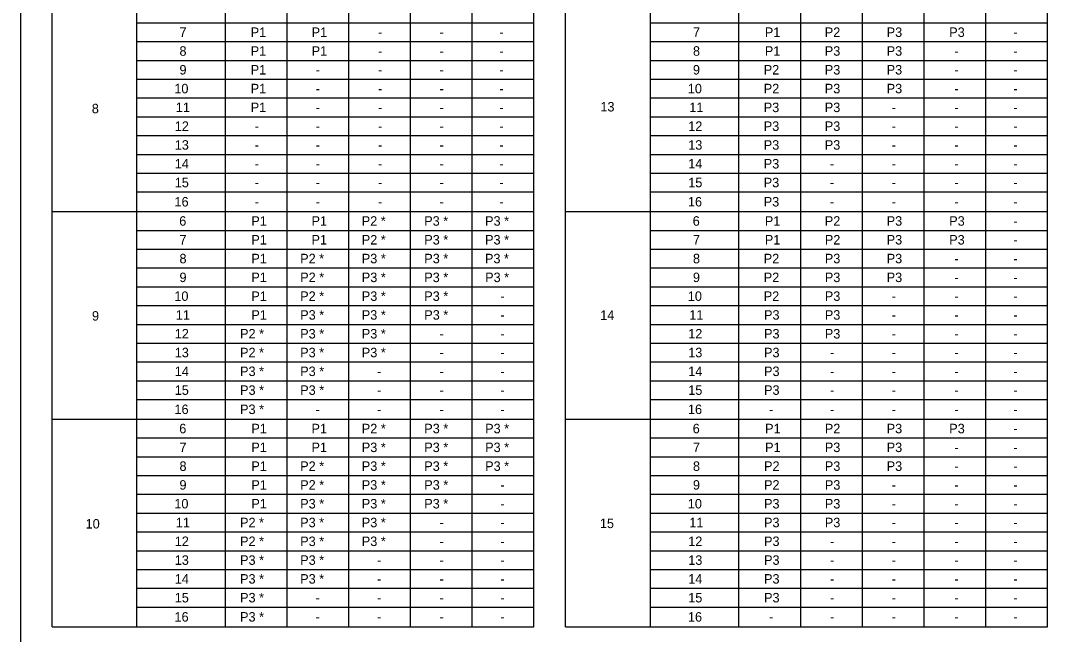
# Model space of a CAD drawing. Extents: x -2340 to 628, y -879 to 309.
# Drawn here: x -1077.4 to -752.7, y -78.6 to 115.5 of the extents above; entities that cross this region are included whole.
import ezdxf

# ---------------------------------------------------------------- set-up
doc = ezdxf.new("R2010")
doc.units = 0
for name, color, linetype in [('Level 1', 7, 'Continuous'), ('Level 2', 7, 'Continuous'), ('Level 30', 7, 'Continuous')]:
    doc.layers.add(name, color=color, linetype=linetype)

msp = doc.modelspace()

# ---------------------------------------------------------------- linework, layer by layer
at = {"layer": 'Level 1'}
for p, q in [((-1077.39, 294.44), (-1077.39, -269.56)), ((-878.24, -76.15), (-878.24, 270.25)), ((-850.23, -76.15), (-850.23, 270.25)), ((-830.72, -76.15), (-830.72, 262.9)), ((-811.22, -76.15), (-811.22, 262.9)), ((-791.71, -76.15), (-791.71, 262.9)), ((-772.2, -76.15), (-772.2, 262.9)), ((-1067.39, -76.15), (-1067.39, 251.9)), ((-915.04, -76.15), (-915.04, 251.9)), ((-905.04, -76.15), (-905.04, 251.9)), ((-752.69, -76.15), (-752.69, 251.9)), ((-878.24, 114.74), (-752.69, 114.74)), ((-878.24, 108.8), (-752.69, 108.8)), ((-878.24, 102.86), (-752.69, 102.86)), ((-878.24, 96.92), (-752.69, 96.92)), ((-878.24, 90.98), (-752.69, 90.98)), ((-878.24, 85.04), (-752.69, 85.04)), ((-878.24, 79.1), (-752.69, 79.1)), ((-878.24, 73.16), (-752.69, 73.16)), ((-878.24, 67.22), (-752.69, 67.22)), ((-878.24, 61.28), (-752.69, 61.28)), ((-974.24, 55.07), (-938.6, 55.07)), ((-938.6, 55.07), (-915.04, 55.07)), ((-905.04, 55.07), (-752.69, 55.07)), ((-878.24, 49.13), (-752.69, 49.13)), ((-878.24, 43.19), (-752.69, 43.19)), ((-878.24, 37.25), (-752.69, 37.25)), ((-878.24, 31.31), (-752.69, 31.31)), ((-878.24, 25.37), (-752.69, 25.37)), ((-878.24, 19.43), (-752.69, 19.43)), ((-878.24, 13.49), (-752.69, 13.49)), ((-878.24, 7.55), (-752.69, 7.55)), ((-878.24, 1.61), (-752.69, 1.61)), ((-878.24, -4.33), (-752.69, -4.33)), ((-905.04, -10.54), (-752.69, -10.54)), ((-878.24, -16.48), (-752.69, -16.48)), ((-878.24, -22.42), (-752.69, -22.42)), ((-878.24, -28.36), (-752.69, -28.36)), ((-878.24, -34.3), (-752.69, -34.3)), ((-878.24, -40.24), (-752.69, -40.24)), ((-878.24, -46.18), (-752.69, -46.18)), ((-878.24, -52.12), (-752.69, -52.12)), ((-878.24, -58.06), (-752.69, -58.06)), ((-878.24, -64), (-752.69, -64)), ((-878.24, -69.94), (-752.69, -69.94)), ((-905.04, -76.15), (-752.69, -76.15))]:
    msp.add_line(p, q, dxfattribs=at)
at = {"layer": 'Level 2'}
for p, q in [((-1040.58, -76.15), (-1040.58, 251.9)), ((-1012.58, -76.15), (-1012.58, 251.9)), ((-993.07, -76.15), (-993.07, 251.9)), ((-973.56, -76.15), (-973.56, 251.9)), ((-954.05, -76.15), (-954.05, 251.9)), ((-934.55, -76.15), (-934.55, 251.9)), ((-1040.58, 114.74), (-915.04, 114.74)), ((-974.24, 114.74), (-938.6, 114.74)), ((-1040.58, 108.8), (-915.04, 108.8)), ((-974.24, 108.8), (-938.6, 108.8)), ((-1040.58, 102.86), (-915.04, 102.86)), ((-974.24, 102.86), (-938.6, 102.86)), ((-1040.58, 96.92), (-915.04, 96.92)), ((-974.24, 96.92), (-938.6, 96.92)), ((-1040.58, 90.98), (-915.04, 90.98)), ((-974.24, 90.98), (-938.6, 90.98)), ((-1040.58, 85.04), (-915.04, 85.04)), ((-1040.58, 79.1), (-915.04, 79.1)), ((-1040.58, 73.16), (-915.04, 73.16)), ((-1040.58, 67.22), (-915.04, 67.22)), ((-1040.58, 61.28), (-915.04, 61.28)), ((-1067.39, 55.07), (-915.04, 55.07)), ((-1040.58, 49.13), (-915.04, 49.13)), ((-1040.58, 43.19), (-915.04, 43.19)), ((-1040.58, 37.25), (-915.04, 37.25)), ((-1040.58, 31.31), (-915.04, 31.31)), ((-1040.58, 25.37), (-915.04, 25.37)), ((-1040.58, 19.43), (-915.04, 19.43)), ((-1040.58, 13.49), (-915.04, 13.49)), ((-1040.58, 7.55), (-915.04, 7.55)), ((-1040.58, 1.61), (-915.04, 1.61)), ((-1040.58, -4.33), (-915.04, -4.33)), ((-1067.39, -10.54), (-915.04, -10.54)), ((-1040.58, -16.48), (-915.04, -16.48)), ((-1040.58, -22.42), (-915.04, -22.42)), ((-1040.58, -28.36), (-915.04, -28.36)), ((-1040.58, -34.3), (-915.04, -34.3)), ((-1040.58, -40.24), (-915.04, -40.24)), ((-1040.58, -46.18), (-915.04, -46.18)), ((-1040.58, -52.12), (-915.04, -52.12)), ((-1040.58, -58.06), (-915.04, -58.06)), ((-1040.58, -64), (-915.04, -64)), ((-1040.58, -69.94), (-915.04, -69.94)), ((-974.24, -69.94), (-938.6, -69.94)), ((-1067.39, -76.15), (-915.04, -76.15))]:
    msp.add_line(p, q, dxfattribs=at)

# ---------------------------------------------------------------- texts
at = {"layer": 'Level 1'}
for s, p in [('P1', (-842.06, 110.27)), ('P2', (-823.1, 110.27)), ('P3', (-803.53, 110.27)), ('P3', (-783.76, 110.27)), ('-', (-763.44, 110.27)), ('P1', (-842.06, 104.33)), ('P3', (-823.1, 104.33)), ('P3', (-803.53, 104.33)), ('-', (-782.14, 104.33)), ('-', (-763.44, 104.33)), ('P2', (-842.4, 98.39)), ('P3', (-823.1, 98.39)), ('P3', (-803.53, 98.39)), ('-', (-782.14, 98.39)), ('-', (-763.44, 98.39)), ('P2', (-842.4, 92.45)), ('P3', (-823.1, 92.45)), ('P3', (-803.53, 92.45)), ('-', (-782.14, 92.45)), ('-', (-763.44, 92.45)), ('13', (-894.06, 86.71)), ('P3', (-842.4, 86.51)), ('P3', (-823.1, 86.51)), ('-', (-801.91, 86.51)), ('-', (-782.14, 86.51)), ('-', (-763.44, 86.51)), ('P3', (-842.4, 80.57)), ('P3', (-823.1, 80.57)), ('-', (-801.91, 80.57)), ('-', (-782.14, 80.57)), ('-', (-763.44, 80.57)), ('P3', (-842.4, 74.63)), ('P3', (-823.1, 74.63)), ('-', (-801.92, 74.63)), ('-', (-782.14, 74.63)), ('-', (-763.44, 74.63)), ('P3', (-842.4, 68.69)), ('-', (-821.48, 68.69)), ('-', (-801.92, 68.69)), ('-', (-782.14, 68.69)), ('-', (-763.44, 68.69)), ('P3', (-842.4, 62.75)), ('-', (-821.48, 62.75)), ('-', (-801.92, 62.75)), ('-', (-782.14, 62.75)), ('-', (-763.44, 62.75)), ('P3', (-842.4, 56.68)), ('-', (-821.48, 56.68)), ('-', (-801.92, 56.68)), ('-', (-782.14, 56.68)), ('-', (-763.44, 56.68)), ('P1', (-842.06, 50.6)), ('P2', (-823.1, 50.6)), ('P3', (-803.53, 50.6)), ('P3', (-783.76, 50.6)), ('-', (-763.44, 50.6)), ('P1', (-842.06, 44.66)), ('P2', (-823.09, 44.66)), ('P3', (-803.53, 44.66)), ('P3', (-783.76, 44.66)), ('-', (-763.44, 44.66)), ('P2', (-842.4, 38.72)), ('P3', (-823.09, 38.72)), ('P3', (-803.53, 38.72)), ('-', (-782.14, 38.72)), ('-', (-763.44, 38.72)), ('P2', (-842.4, 32.78)), ('P3', (-823.09, 32.78)), ('P3', (-803.53, 32.78)), ('-', (-782.14, 32.78)), ('-', (-763.44, 32.78)), ('P2', (-842.4, 26.84)), ('P3', (-823.09, 26.84)), ('-', (-801.92, 26.84)), ('-', (-782.14, 26.84)), ('-', (-763.44, 26.84)), ('14', (-894.11, 20.82)), ('P3', (-842.31, 20.9)), ('P3', (-823.09, 20.9)), ('-', (-801.92, 20.9)), ('-', (-782.14, 20.9)), ('-', (-763.44, 20.9)), ('P3', (-842.31, 14.96)), ('P3', (-823.09, 14.96)), ('-', (-801.92, 14.96)), ('-', (-782.14, 14.96)), ('-', (-763.44, 14.96)), ('P3', (-842.31, 9.02)), ('-', (-821.47, 9.02)), ('-', (-801.92, 9.02)), ('-', (-782.13, 9.02)), ('-', (-763.44, 9.02)), ('P3', (-842.31, 3.08)), ('-', (-821.47, 3.08)), ('-', (-801.92, 3.08)), ('-', (-782.13, 3.08)), ('-', (-763.44, 3.08)), ('P3', (-842.31, -2.86)), ('-', (-821.47, -2.86)), ('-', (-801.92, -2.86)), ('-', (-782.13, -2.86)), ('-', (-763.44, -2.86)), ('-', (-840.7, -8.93)), ('-', (-821.47, -8.93)), ('-', (-801.92, -8.93)), ('-', (-782.13, -8.93)), ('-', (-763.44, -8.93)), ('P1', (-841.97, -15.01)), ('P2', (-823.09, -15.01)), ('P3', (-803.53, -15.01)), ('P3', (-783.75, -15.01)), ('-', (-763.44, -15.01)), ('P1', (-841.97, -20.95)), ('P3', (-823.09, -20.95)), ('P3', (-803.53, -20.95)), ('-', (-782.13, -20.95)), ('-', (-763.44, -20.95)), ('P2', (-842.31, -26.89)), ('P3', (-823.09, -26.89)), ('P3', (-803.53, -26.89)), ('-', (-782.13, -26.89)), ('-', (-763.44, -26.89)), ('P2', (-842.31, -32.83)), ('P3', (-823.09, -32.83)), ('-', (-801.92, -32.83)), ('-', (-782.13, -32.83)), ('-', (-763.44, -32.83)), ('P3', (-842.31, -38.77)), ('P3', (-823.09, -38.77)), ('-', (-801.92, -38.77)), ('-', (-782.13, -38.77)), ('-', (-763.44, -38.77)), ('15', (-894.21, -44.98)), ('P3', (-842.31, -44.71)), ('P3', (-823.09, -44.71)), ('-', (-801.92, -44.71)), ('-', (-782.13, -44.71)), ('-', (-763.44, -44.71)), ('P3', (-842.31, -50.65)), ('-', (-821.47, -50.65)), ('-', (-801.92, -50.65)), ('-', (-782.13, -50.65)), ('-', (-763.44, -50.65)), ('P3', (-842.31, -56.59)), ('-', (-821.47, -56.59)), ('-', (-801.92, -56.59)), ('-', (-782.13, -56.59)), ('-', (-763.44, -56.59)), ('P3', (-842.31, -62.53)), ('-', (-821.47, -62.53)), ('-', (-801.92, -62.53)), ('-', (-782.13, -62.53)), ('-', (-763.44, -62.53)), ('P3', (-842.31, -68.47)), ('-', (-821.47, -68.47)), ('-', (-801.92, -68.47)), ('-', (-782.13, -68.47)), ('-', (-763.44, -68.47)), ('-', (-840.7, -74.54)), ('-', (-821.47, -74.54)), ('-', (-801.92, -74.54)), ('-', (-782.13, -74.54)), ('-', (-763.44, -74.54))]:
    msp.add_text(s, height=3, dxfattribs=at).set_placement(p)
at = {"layer": 'Level 2'}
for s, p in [('7', (-1027.13, 110.27)), ('P1', (-1004.62, 110.27)), ('P1', (-985.35, 110.27)), ('-', (-964.36, 110.27)), ('-', (-944.91, 110.27)), ('-', (-925.97, 110.27)), ('7', (-864.78, 110.27)), ('8', (-1027.13, 104.33)), ('P1', (-1004.62, 104.33)), ('P1', (-985.35, 104.33)), ('8', (-864.78, 104.33)), ('-', (-964.36, 104.33)), ('-', (-944.91, 104.33)), ('-', (-925.97, 104.33)), ('9', (-1027.14, 98.39)), ('P1', (-1004.62, 98.39)), ('9', (-864.79, 98.39)), ('-', (-984.07, 98.39)), ('-', (-964.36, 98.39)), ('-', (-944.91, 98.39)), ('-', (-925.97, 98.39)), ('10', (-1028.76, 92.45)), ('P1', (-1004.62, 92.45)), ('10', (-866.41, 92.45)), ('-', (-984.07, 92.45)), ('-', (-964.36, 92.45)), ('-', (-944.91, 92.45)), ('-', (-925.97, 92.45)), ('8', (-1054.85, 86.14)), ('11', (-1028.29, 86.51)), ('P1', (-1004.62, 86.51)), ('-', (-984.07, 86.51)), ('-', (-964.36, 86.51)), ('-', (-944.91, 86.51)), ('-', (-925.97, 86.51)), ('11', (-865.94, 86.51)), ('12', (-1028.63, 80.57)), ('-', (-1003.34, 80.57)), ('-', (-984.07, 80.57)), ('-', (-964.36, 80.57)), ('-', (-944.91, 80.57)), ('-', (-925.97, 80.57)), ('12', (-866.28, 80.57)), ('13', (-1028.63, 74.63)), ('-', (-1003.34, 74.63)), ('-', (-984.07, 74.63)), ('-', (-964.36, 74.63)), ('-', (-944.91, 74.63)), ('-', (-925.97, 74.63)), ('13', (-866.28, 74.63)), ('14', (-1028.63, 68.69)), ('14', (-866.28, 68.69)), ('-', (-1003.34, 68.69)), ('-', (-984.07, 68.69)), ('-', (-964.36, 68.69)), ('-', (-944.91, 68.69)), ('-', (-925.97, 68.69)), ('15', (-1028.63, 62.75)), ('15', (-866.28, 62.75)), ('-', (-1003.34, 62.75)), ('-', (-984.07, 62.75)), ('-', (-964.36, 62.75)), ('-', (-944.91, 62.75)), ('-', (-925.97, 62.75)), ('16', (-1028.71, 56.68)), ('16', (-866.36, 56.68)), ('-', (-1003.34, 56.68)), ('-', (-984.07, 56.68)), ('-', (-964.36, 56.68)), ('-', (-944.91, 56.68)), ('-', (-925.97, 56.68)), ('P1', (-1004.42, 50.6)), ('P1', (-985.39, 50.6)), ('P2 *', (-969.51, 50.6)), ('P3 *', (-949.76, 50.6)), ('P3 *', (-930.51, 50.6)), ('7', (-1027.13, 44.66)), ('P1', (-1004.41, 44.66)), ('P1', (-985.39, 44.66)), ('P2 *', (-969.49, 44.66)), ('P3 *', (-949.74, 44.66)), ('P3 *', (-930.51, 44.66)), ('7', (-864.78, 44.66)), ('8', (-1027.13, 38.72)), ('P1', (-1004.41, 38.72)), ('P2 *', (-988.97, 38.72)), ('P3 *', (-969.49, 38.72)), ('P3 *', (-949.74, 38.72)), ('P3 *', (-930.54, 38.72)), ('8', (-864.78, 38.72)), ('9', (-1027.14, 32.78)), ('P1', (-1004.41, 32.78)), ('P2 *', (-988.97, 32.78)), ('P3 *', (-969.49, 32.78)), ('P3 *', (-949.74, 32.78)), ('P3 *', (-930.49, 32.78)), ('9', (-864.79, 32.78)), ('10', (-1028.76, 26.84)), ('P1', (-1004.41, 26.84)), ('P2 *', (-988.97, 26.84)), ('P3 *', (-969.49, 26.84)), ('P3 *', (-949.74, 26.84)), ('10', (-866.41, 26.84)), ('-', (-925.64, 26.84)), ('9', (-1054.79, 20.6)), ('11', (-1028.29, 20.9)), ('P1', (-1004.41, 20.9)), ('P3 *', (-988.97, 20.9)), ('P3 *', (-969.49, 20.9)), ('P3 *', (-949.74, 20.9)), ('11', (-865.94, 20.9)), ('-', (-925.64, 20.9)), ('12', (-1028.63, 14.96)), ('P2 *', (-1007.98, 14.96)), ('P3 *', (-988.97, 14.96)), ('P3 *', (-969.49, 14.96)), ('-', (-944.89, 14.96)), ('-', (-925.64, 14.96)), ('12', (-866.28, 14.96)), ('13', (-1028.63, 9.02)), ('P2 *', (-1007.98, 9.02)), ('P3 *', (-988.97, 9.02)), ('P3 *', (-969.49, 9.02)), ('-', (-944.89, 9.02)), ('-', (-925.64, 9.02)), ('13', (-866.28, 9.02)), ('14', (-1028.63, 3.08)), ('P3 *', (-1007.98, 3.08)), ('P3 *', (-988.97, 3.08)), ('-', (-964.64, 3.08)), ('-', (-944.89, 3.08)), ('-', (-925.64, 3.08)), ('14', (-866.28, 3.08)), ('15', (-1028.63, -2.86)), ('P3 *', (-1007.98, -2.86)), ('P3 *', (-988.97, -2.86)), ('15', (-866.28, -2.86)), ('-', (-964.64, -2.86)), ('-', (-944.89, -2.86)), ('-', (-925.64, -2.86)), ('16', (-1028.71, -8.93)), ('P3 *', (-1007.98, -8.93)), ('16', (-866.36, -8.93)), ('-', (-984.12, -8.93)), ('-', (-964.64, -8.93)), ('-', (-944.89, -8.93)), ('-', (-925.64, -8.93)), ('P1', (-1004.41, -15.01)), ('P1', (-985.39, -15.01)), ('P2 *', (-969.49, -15.01)), ('P3 *', (-949.74, -15.01)), ('P3 *', (-930.49, -15.01)), ('7', (-1027.13, -20.95)), ('P1', (-1004.41, -20.95)), ('P1', (-985.39, -20.95)), ('P3 *', (-969.49, -20.95)), ('P3 *', (-949.74, -20.95)), ('P3 *', (-930.49, -20.95)), ('7', (-864.78, -20.95)), ('8', (-1027.13, -26.89)), ('P1', (-1004.41, -26.89)), ('P2 *', (-988.97, -26.89)), ('P3 *', (-969.49, -26.89)), ('P3 *', (-949.74, -26.89)), ('P3 *', (-930.49, -26.89)), ('8', (-864.78, -26.89)), ('9', (-1027.14, -32.83)), ('P1', (-1004.41, -32.83)), ('P2 *', (-988.97, -32.83)), ('P3 *', (-969.49, -32.83)), ('P3 *', (-949.74, -32.83)), ('-', (-925.64, -32.83)), ('9', (-864.79, -32.83)), ('10', (-1028.76, -38.77)), ('P1', (-1004.41, -38.77)), ('P3 *', (-988.97, -38.77)), ('P3 *', (-969.49, -38.77)), ('P3 *', (-949.74, -38.77)), ('-', (-925.64, -38.77)), ('10', (-866.41, -38.77)), ('10', (-1056.81, -45.11)), ('11', (-1028.29, -44.71)), ('P2 *', (-1007.98, -44.71)), ('P3 *', (-988.97, -44.71)), ('P3 *', (-969.49, -44.71)), ('11', (-865.94, -44.71)), ('-', (-944.89, -44.71)), ('-', (-925.64, -44.71)), ('12', (-1028.63, -50.65)), ('P2 *', (-1007.98, -50.65)), ('P3 *', (-988.97, -50.65)), ('P3 *', (-969.49, -50.65)), ('12', (-866.28, -50.65)), ('-', (-944.89, -50.65)), ('-', (-925.64, -50.65)), ('13', (-1028.63, -56.59)), ('P3 *', (-1007.98, -56.59)), ('P3 *', (-988.97, -56.59)), ('13', (-866.28, -56.59)), ('-', (-964.64, -56.59)), ('-', (-944.89, -56.59)), ('-', (-925.64, -56.59)), ('14', (-1028.63, -62.53)), ('P3 *', (-1007.98, -62.53)), ('P3 *', (-988.97, -62.53)), ('-', (-964.64, -62.53)), ('-', (-944.89, -62.53)), ('-', (-925.64, -62.53)), ('14', (-866.28, -62.53)), ('15', (-1028.63, -68.47)), ('P3 *', (-1007.98, -68.47)), ('-', (-984.12, -68.47)), ('-', (-964.64, -68.47)), ('-', (-944.89, -68.47)), ('-', (-925.64, -68.47)), ('15', (-866.28, -68.47)), ('16', (-1028.71, -74.54)), ('P3 *', (-1007.98, -74.54)), ('-', (-984.12, -74.54)), ('-', (-964.64, -74.54)), ('-', (-944.89, -74.54)), ('-', (-925.64, -74.54)), ('16', (-866.36, -74.54))]:
    msp.add_text(s, height=3, dxfattribs=at).set_placement(p)
at = {"layer": 'Level 30'}
for p in [(-1027.21, 50.6), (-864.86, 50.6), (-1027.21, -15.01), (-864.86, -15.01)]:
    msp.add_text('6', height=3, dxfattribs=at).set_placement(p)

doc.saveas('drawing.dxf')
